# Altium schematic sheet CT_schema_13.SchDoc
size 389 x 278 mm
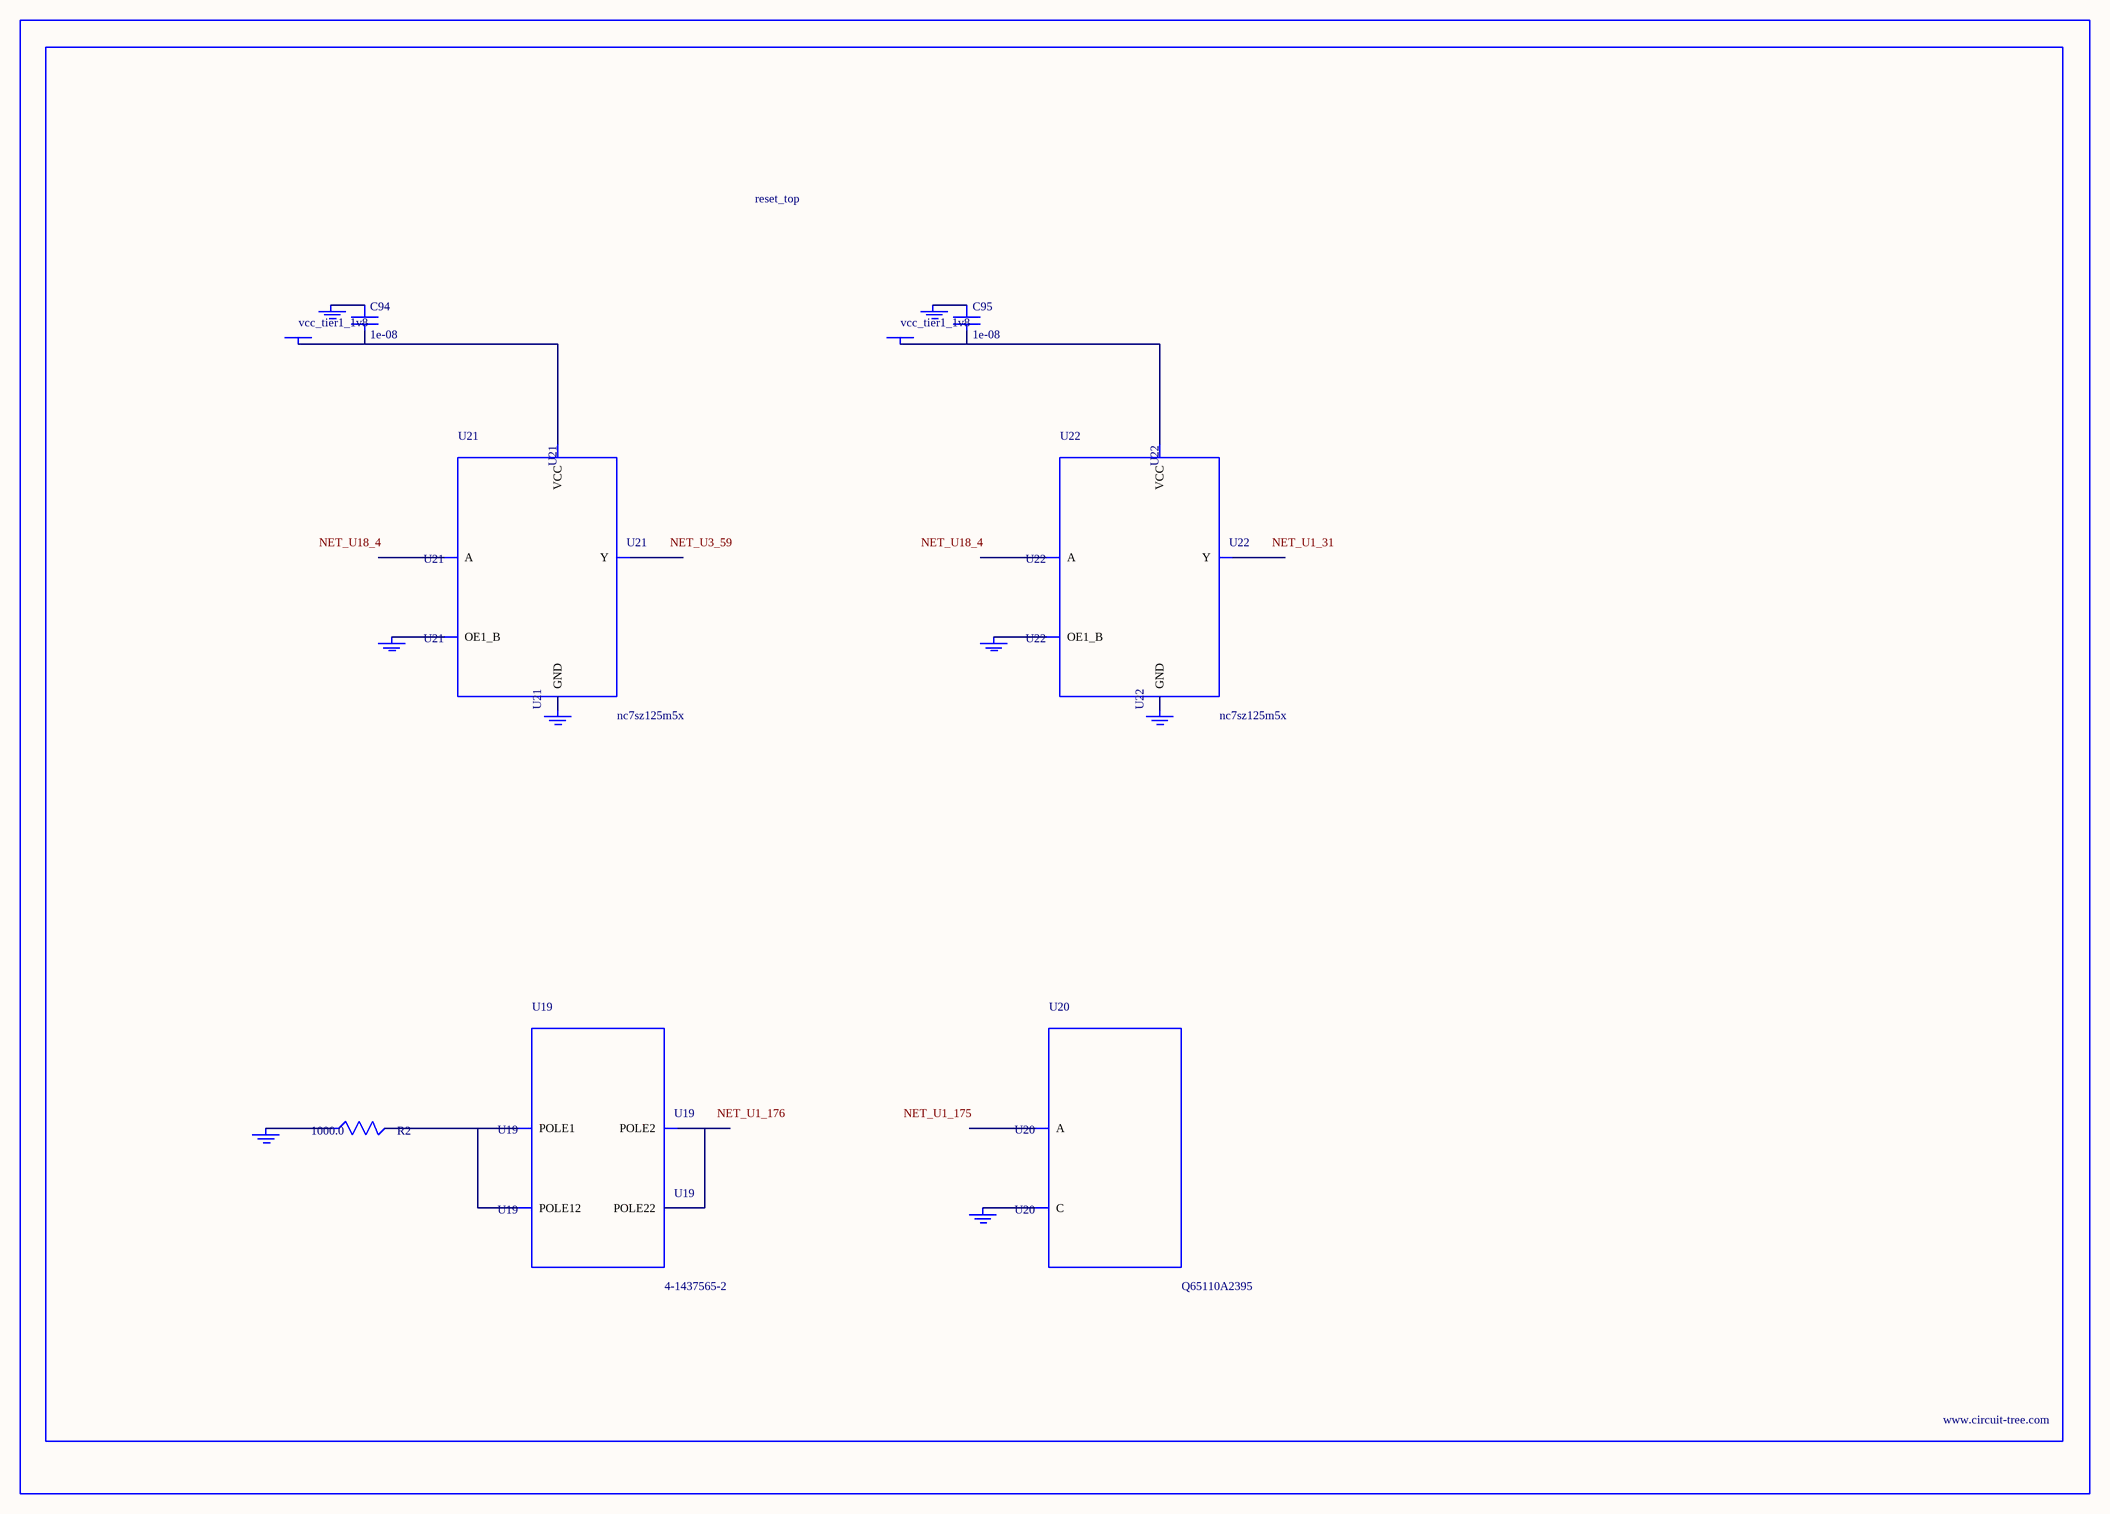
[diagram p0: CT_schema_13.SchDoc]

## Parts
BORDER12  (no value)
C94  1e-08  [C0402]
C95  1e-08  [C0402]
GND_INSTANCE_12_0  (no value)
GND_INSTANCE_12_1  (no value)
GND_INSTANCE_12_2  (no value)
GND_INSTANCE_12_3  (no value)
GND_INSTANCE_12_4  (no value)
GND_INSTANCE_12_5  (no value)
GND_INSTANCE_12_6  (no value)
GND_INSTANCE_12_7  (no value)
POWER_INSTANCE_12_0  vcc_tier1_1v8
POWER_INSTANCE_12_1  vcc_tier1_1v8
R2  1000.0  [R0603]
U19  4-1437565-2  [SW_4-1437565-2]
U20  Q65110A2395  [LGM67K-G1J2-24-Z]
U21  nc7sz125m5x  [NC7SZ125M5X]
U22  nc7sz125m5x  [NC7SZ125M5X]

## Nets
NetC94_1: C94.1 GND_INSTANCE_12_2.0(GND)
NetC94_2: C94.2 POWER_INSTANCE_12_0.0(PWR) U21.5(VCC)
NetC95_1: C95.1 GND_INSTANCE_12_5.0(GND)
NetC95_2: C95.2 POWER_INSTANCE_12_1.0(PWR) U22.5(VCC)
NetGND_INSTANCE_12_0_0: GND_INSTANCE_12_0.0(GND) R2.1
NetGND_INSTANCE_12_1_0: GND_INSTANCE_12_1.0(GND) U20.C
NetGND_INSTANCE_12_3_0: GND_INSTANCE_12_3.0(GND) U21.1(OE1_B)
NetGND_INSTANCE_12_4_0: GND_INSTANCE_12_4.0(GND) U21.3(GND)
NetGND_INSTANCE_12_6_0: GND_INSTANCE_12_6.0(GND) U22.1(OE1_B)
NetGND_INSTANCE_12_7_0: GND_INSTANCE_12_7.0(GND) U22.3(GND)
NetR2_2: R2.2 U19.1(POLE1) U19.2(POLE12)
NetU19_3: U19.3(POLE2) U19.4(POLE22)

Not connected (* = marked no-connect by the designer): U20 A; U21 2(A) 4(Y); U22 2(A) 4(Y)

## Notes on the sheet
- Labels drawn without touching a wire or pin: NET_U1_31, NET_U1_175, NET_U1_176, NET_U3_59, NET_U18_4

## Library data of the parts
BORDER12 = BORDER_PAGE12
C94 C95 = C0402C103K3RAC
GND_INSTANCE_12_0-GND_INSTANCE_12_7 = GND
POWER_INSTANCE_12_0 POWER_INSTANCE_12_1 = PWR
R2 = RC0603JR-071KL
